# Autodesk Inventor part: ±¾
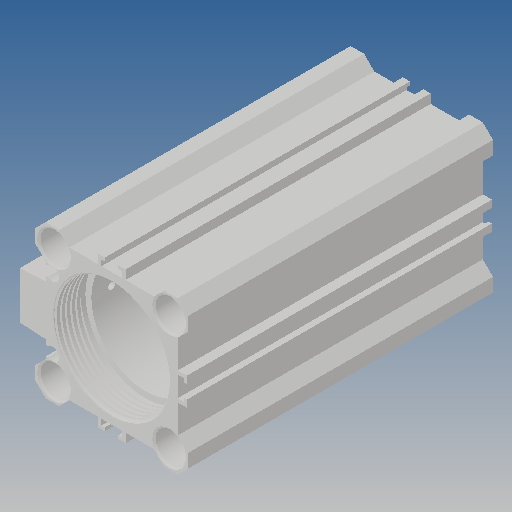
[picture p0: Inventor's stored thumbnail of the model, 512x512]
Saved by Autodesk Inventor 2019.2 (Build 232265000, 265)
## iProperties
Created: 2013-09
Part Number: ±¾
Material: Ogólny
Document SubType Name: Modeling
Designer: CADENGINEERING4
Density: 1 g/cm^3
Appearance: Domyślna
Author: CADENGINEERING4
Revision Number: ÈÎºÎ
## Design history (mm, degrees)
feature "¾µÏò3"
node "Bryła1"
